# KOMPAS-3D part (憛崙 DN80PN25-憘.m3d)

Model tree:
1. Объединить компоненты:1  (labels: СЕНС DN80PN25)
2. Эскиз:1
3. Операция выдавливания:1
     Расстояние 1 = 14
4. Фаска:1
     Угол = 45; Длина 1 = 2; Длина 2 = 2

Referenced files in D:\Савин\!СЕНСОР\3D для заказчика\!Новый перечень\СЕНС\1. СЕНС\DN80\: СЕНС DN80PN25.a3d
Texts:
  СЕНС DN80PN25-СВ
  ООО НПП Сенсор
  СЕНС DN80PN25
